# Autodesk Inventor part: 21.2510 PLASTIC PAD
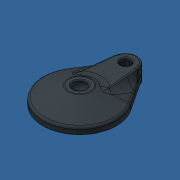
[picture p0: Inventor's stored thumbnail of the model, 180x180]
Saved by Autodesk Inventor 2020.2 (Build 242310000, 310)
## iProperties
Created: 2015-09
Part Number: 21.2510 PLASTIC PAD
Material: PA 6
Document SubType Name: Modeling
Designer: MuellerJ
Mass: 39.9956 g
Surface Area: 210.133 cm^2
Volume: 37.7317 cm^3
Density: 1.06 g/cm^3
Appearance: RAL 7012 Basaltgrau
Description: 21.2510 PLASTIC PAD
Beschreibung: Teller D 80 MT grau mit Bohrung
Bezeichnung: Teller D 80 MT grau mit Bohrung
Artikelnr: 212327/0
Lieferantennr: 72401
Zeichnungsnr: 21-2327-0FZ.000
MiniTec_ID: 212327/0
Teileart: K
Lieferant: MiniTec
Author: MuellerJ
Title: Teller D 80 MT grau mit Bohrung
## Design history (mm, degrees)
feature "Basis1"
feature "Körper verschieben1"
node "3638"
other parameters: "d0" = 74.125, "d1" = -140.751
